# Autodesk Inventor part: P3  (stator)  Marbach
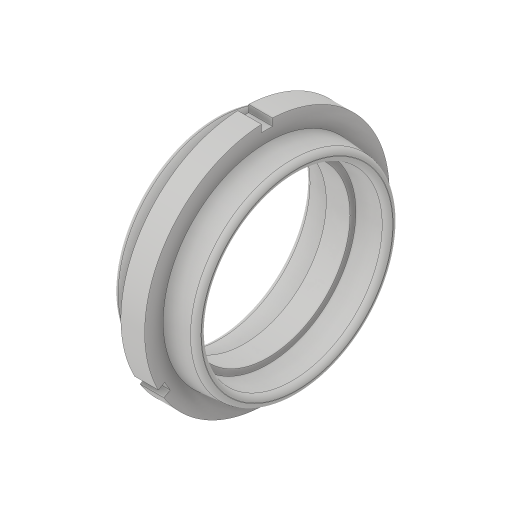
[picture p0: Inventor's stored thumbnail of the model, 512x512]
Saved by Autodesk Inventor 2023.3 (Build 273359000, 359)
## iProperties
Created: 2017-10
Part Number: P3  (stator)  Marbach
Material: Générique
Document SubType Name: Modeling
Designer: geoffroy.marbach
Density: 1 g/cm^3
Appearance: Par défaut
Author: geoffroy.marbach
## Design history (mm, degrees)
sketch "Sketch1"
  geometry: L1 (-2.351, 13.529)-(-2.351, 3.369); L2 (-2.351, 3.369)-(-17.857, 2.012); L3 (-17.857, 2.012)-(-17.857, -3.872); L4 (-17.857, -3.872)-(-1.857, -5.271); L5 (-1.857, -5.271)-(-1.857, -8.471); L6 (-1.857, -8.471)-(11.143, -8.471); L7 (11.143, -8.471)-(11.143, -5.271); L8 (11.143, -5.271)-(27.143, -3.872); L9 (27.143, -3.872)-(27.143, 1.926); L10 (27.143, 1.926)-(10.649, 3.369); L11 (10.649, 3.369)-(10.649, 13.529); L12 (10.649, 13.529)-(-2.351, 13.529); L13 (-55.543, -53.471)-(74.938, -53.471)
  constraints: 26 end point, 5 parallel, 3 perpendicular, 1 horizontal, 1 vertical
  dimensions: "d0" = 13 distance of L11.end L1.start; "d1" = 13 distance of L5.end L6.end; "d2" = 95 deg angle of L10 L11; "d3" = 95 deg angle of L2 L1; "d4" = 95 deg angle of L5 L4; "d5" = 16 distance between parallel lines of L7 L9; "d6" = 16 distance between parallel lines of L5 L3; "d7" = 90 diameter of L6 L13; "d8" = 96.4 diameter of L7.end L13; "d9" = 96.4 diameter of L4.end L13; "d10" = 113.68 diameter of L10.end L13; "d11" = 113.68 diameter of L1.end L13; "d12" = 134 diameter of L12 L13
revolve "Revolution1" sketch "Sketch1" stored, may be unused: angle "d13" = 90 deg
fillet "Fillet1" dims "d14" = 3
fillet "Fillet2" dims "d15" = 3
sketch "Sketch2"
  geometry: L1 (-3, 69.999)-(3, 69.999); L2 (3, 69.999)-(3, 63); L3 (3, 63)-(-3, 63); L4 (-3, 63)-(-3, 69.999); C1 r 45 at (0, 0) reference; 1 further point
  constraints: 8 end point, 2 parallel, 1 horizontal, 1 perpendicular
  dimensions: "d16" = 63 distance from line of C1.centre L3; "d17" = 6 distance of L1.start L1.end; "d18" = 3 distance from line of C1.centre L2 (= 0.5 x d17)
extrude "Extrusion1" cut sketch "Sketch2" extent not by distance; stored distance "d19" = 13; taper "d20" = 0 deg
pattern_circular "Circular Pattern2" dims angle "d25" = 360 deg
body "Solid1"
